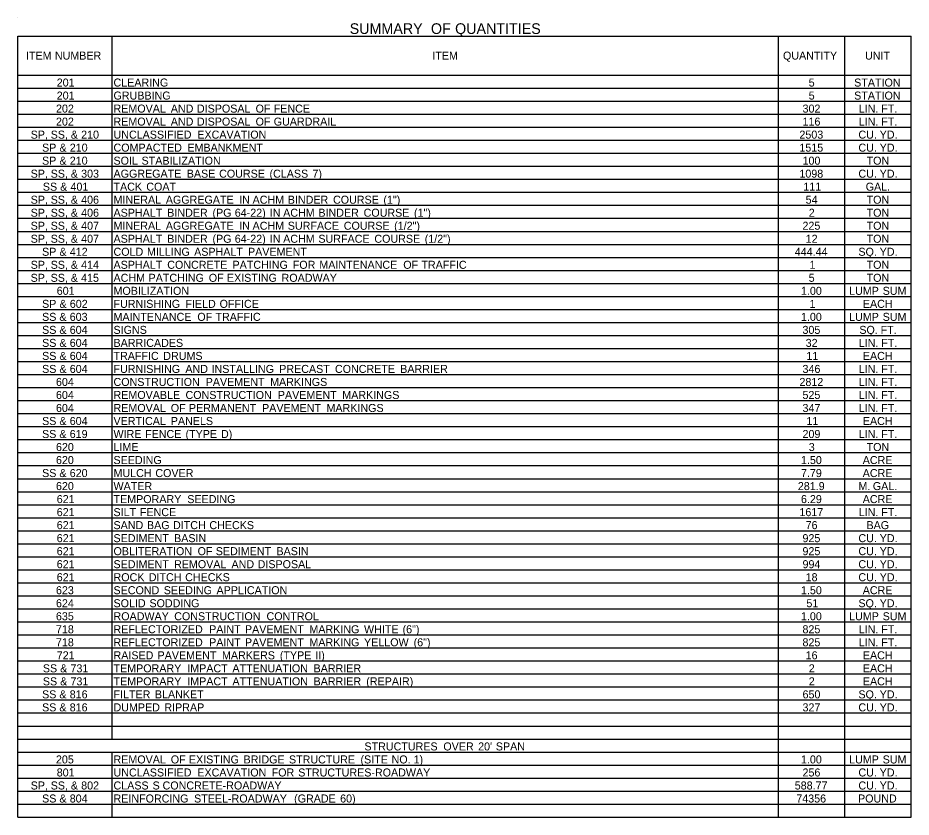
# Model space of a CAD drawing. Extents: x 120 to 5602, y 34 to 1048.
# Drawn here: x 4195 to 4864, y 243 to 842 of the extents above; entities that cross this region are included whole.
import ezdxf

# ---------------------------------------------------------------- set-up
doc = ezdxf.new("R2010")
doc.units = 0
doc.layers.add('Default', color=7, linetype='Continuous')
doc.layers.add('STAMP', color=7, linetype='Continuous')

msp = doc.modelspace()

# ---------------------------------------------------------------- linework, layer by layer
at = {"layer": 'Default'}
for p, q in [((4194.64, 828.32), (4265.32, 828.32)), ((4194.64, 828.32), (4863.97, 828.32)), ((4194.64, 243.32), (4194.64, 828.32)), ((4265.32, 301.82), (4265.32, 828.32)), ((4764.52, 243.32), (4764.52, 828.32)), ((4814.25, 243.32), (4814.25, 828.32)), ((4814.25, 301.82), (4814.25, 828.32)), ((4863.97, 243.32), (4863.97, 828.32)), ((4194.64, 799.07), (4863.97, 799.07)), ((4265.32, 301.82), (4265.32, 799.07)), ((4764.52, 301.82), (4764.52, 799.07)), ((4194.64, 789.32), (4863.97, 789.32)), ((4194.64, 779.57), (4863.97, 779.57)), ((4194.64, 769.82), (4863.97, 769.82)), ((4194.64, 760.07), (4863.97, 760.07)), ((4194.64, 750.32), (4863.97, 750.32)), ((4194.64, 740.57), (4863.97, 740.57)), ((4194.64, 730.82), (4863.97, 730.82)), ((4194.64, 721.07), (4863.97, 721.07)), ((4194.64, 711.32), (4863.97, 711.32)), ((4194.64, 701.57), (4863.97, 701.57)), ((4194.64, 691.82), (4863.97, 691.82)), ((4194.64, 682.07), (4863.97, 682.07)), ((4194.64, 672.32), (4863.97, 672.32)), ((4194.64, 662.57), (4863.97, 662.57)), ((4194.64, 652.82), (4863.97, 652.82)), ((4194.64, 643.07), (4863.97, 643.07)), ((4194.64, 633.32), (4863.97, 633.32)), ((4194.64, 623.57), (4863.97, 623.57)), ((4194.64, 613.82), (4863.97, 613.82)), ((4194.64, 604.07), (4863.97, 604.07)), ((4194.64, 594.32), (4863.97, 594.32)), ((4194.64, 584.57), (4863.97, 584.57)), ((4194.64, 574.82), (4863.97, 574.82)), ((4194.64, 565.07), (4863.97, 565.07)), ((4194.64, 555.32), (4863.97, 555.32)), ((4194.64, 545.57), (4863.97, 545.57)), ((4194.64, 535.82), (4863.97, 535.82)), ((4194.64, 526.07), (4863.97, 526.07)), ((4194.64, 516.32), (4863.97, 516.32)), ((4194.64, 506.57), (4863.97, 506.57)), ((4194.64, 496.82), (4863.97, 496.82)), ((4194.64, 487.07), (4863.97, 487.07)), ((4194.64, 477.32), (4863.97, 477.32)), ((4194.64, 467.57), (4863.97, 467.57)), ((4194.64, 457.82), (4863.97, 457.82)), ((4194.64, 448.07), (4863.97, 448.07)), ((4194.64, 438.32), (4863.97, 438.32)), ((4194.64, 428.57), (4863.97, 428.57)), ((4194.64, 418.82), (4863.97, 418.82)), ((4194.64, 409.07), (4863.97, 409.07)), ((4194.64, 399.32), (4863.97, 399.32)), ((4194.64, 389.57), (4863.97, 389.57)), ((4194.64, 379.82), (4863.97, 379.82)), ((4194.64, 370.07), (4863.97, 370.07)), ((4194.64, 360.32), (4863.97, 360.32)), ((4194.64, 350.57), (4863.97, 350.57)), ((4194.64, 340.82), (4863.97, 340.82)), ((4194.64, 331.07), (4863.97, 331.07)), ((4194.64, 321.32), (4863.97, 321.32)), ((4194.64, 311.57), (4863.97, 311.57)), ((4194.64, 301.82), (4863.97, 301.82)), ((4814.25, 301.82), (4863.97, 301.82)), ((4194.64, 292.07), (4863.97, 292.07)), ((4265.32, 243.32), (4265.32, 292.07)), ((4265.32, 243.32), (4265.32, 292.07)), ((4764.52, 243.32), (4764.52, 292.07)), ((4814.25, 243.32), (4814.25, 292.07)), ((4194.64, 282.32), (4863.97, 282.32)), ((4194.64, 272.57), (4863.97, 272.57)), ((4194.64, 262.82), (4863.97, 262.82)), ((4194.64, 253.07), (4863.97, 253.07)), ((4194.64, 243.32), (4863.97, 243.32))]:
    msp.add_line(p, q, dxfattribs=at)
at = {"layer": 'STAMP'}
msp.add_line((4194.64, 841.97), (4194.64, 841.97), dxfattribs=at)

# ---------------------------------------------------------------- texts
at = {"layer": 'Default'}
for s, height, p in [(' SUMMARY', 8, (4440.3, 829.92)), (' OF', 8, (4501.18, 829.92)), (' QUANTITIES', 8, (4519.29, 829.92)), ('ITEM', 6, (4200.72, 810.69)), (' NUMBER', 6, (4220.15, 810.69)), ('ITEM', 6, (4505.21, 810.69)), ('QUANTITY', 6, (4767.95, 810.69)), ('UNIT', 6, (4829.42, 810.69)), ('201', 6, (4223.76, 790.52)), ('CLEARING', 6, (4266.3, 790.52)), ('5', 6, (4787.22, 790.52)), ('STATION', 6, (4821.29, 790.52)), ('201', 6, (4223.76, 780.77)), ('GRUBBING', 6, (4266.3, 780.77)), ('5', 6, (4787.22, 780.77)), ('STATION', 6, (4821.29, 780.77)), ('202', 6, (4223.21, 771.02)), ('REMOVAL', 6, (4266.3, 771.02)), (' AND', 6, (4307, 771.02)), (' DISPOSAL', 6, (4326.58, 771.02)), (' OF', 6, (4370.55, 771.02)), (' FENCE', 6, (4384.13, 771.02)), ('302', 6, (4782.62, 771.02)), ('LIN.', 6, (4824.71, 771.02)), (' FT.', 6, (4839.35, 771.02)), ('202', 6, (4223.21, 761.27)), ('REMOVAL', 6, (4266.3, 761.27)), (' AND', 6, (4307, 761.27)), (' DISPOSAL', 6, (4326.58, 761.27)), (' OF', 6, (4370.55, 761.27)), (' GUARDRAIL', 6, (4384.13, 761.27)), ('116', 6, (4782.59, 761.27)), ('LIN.', 6, (4824.71, 761.27)), (' FT.', 6, (4839.35, 761.27)), ('SP,', 6, (4204.23, 751.52)), (' SS,', 6, (4217, 751.52)), (' &', 6, (4232.09, 751.52)), (' 210', 6, (4239.82, 751.52)), ('UNCLASSIFIED', 6, (4266.3, 751.52)), (' EXCAVATION', 6, (4326.88, 751.52)), ('2503', 6, (4780.26, 751.52)), ('CU.', 6, (4824.47, 751.52)), (' YD.', 6, (4838.18, 751.52)), ('SP', 6, (4212.75, 741.77)), (' &', 6, (4223.57, 741.77)), (' 210', 6, (4231.3, 741.77)), ('COMPACTED', 6, (4266.3, 741.77)), (' EMBANKMENT', 6, (4319.42, 741.77)), ('1515', 6, (4780.23, 741.77)), ('CU.', 6, (4824.47, 741.77)), (' YD.', 6, (4838.18, 741.77)), ('SP', 6, (4212.75, 732.02)), (' &', 6, (4223.57, 732.02)), (' 210', 6, (4231.3, 732.02)), ('SOIL', 6, (4266.3, 732.02)), (' STABILIZATION', 6, (4285.1, 732.02)), ('100', 6, (4782.6, 732.02)), ('TON', 6, (4830.6, 732.02)), ('SP,', 6, (4204.22, 722.27)), (' SS,', 6, (4216.99, 722.27)), (' &', 6, (4232.08, 722.27)), (' 303', 6, (4239.81, 722.27)), ('AGGREGATE', 6, (4266.3, 722.27)), (' BASE', 6, (4318.96, 722.27)), (' COURSE', 6, (4343.21, 722.27)), (' (CLASS', 6, (4380.97, 722.27)), (' 7)', 6, (4413.14, 722.27)), ('1098', 6, (4780.25, 722.27)), ('CU.', 6, (4824.47, 722.27)), (' YD.', 6, (4838.18, 722.27)), ('SS', 6, (4213.36, 712.52)), (' &', 6, (4224.1, 712.52)), (' 401', 6, (4231.83, 712.52)), ('TACK', 6, (4266.3, 712.52)), (' COAT', 6, (4288.64, 712.52)), ('111', 6, (4783.17, 712.52)), ('GAL.', 6, (4829.93, 712.52)), ('SP,', 6, (4204.22, 702.77)), (' SS,', 6, (4216.99, 702.77)), (' &', 6, (4232.08, 702.77)), (' 406', 6, (4239.81, 702.77)), ('MINERAL', 6, (4266.3, 702.77)), (' AGGREGATE', 6, (4303.27, 702.77)), (' IN', 6, (4358.26, 702.77)), (' ACHM', 6, (4368.28, 702.77)), (' BINDER', 6, (4394.67, 702.77)), (' COURSE', 6, (4428.56, 702.77)), (' (1")', 6, (4466.31, 702.77)), ('54', 6, (4784.93, 702.77)), ('TON', 6, (4830.6, 702.77)), ('SP,', 6, (4204.22, 693.02)), (' SS,', 6, (4216.99, 693.02)), (' &', 6, (4232.08, 693.02)), (' 406', 6, (4239.81, 693.02)), ('ASPHALT', 6, (4266.3, 693.02)), (' BINDER', 6, (4304.34, 693.02)), (' (PG', 6, (4338.23, 693.02)), (' 64-22)', 6, (4354.94, 693.02)), (' IN', 6, (4381.18, 693.02)), (' ACHM', 6, (4391.2, 693.02)), (' BINDER', 6, (4417.59, 693.02)), (' COURSE', 6, (4451.48, 693.02)), (' (1")', 6, (4489.23, 693.02)), ('2', 6, (4787.28, 693.02)), ('TON', 6, (4830.6, 693.02)), (' (1/2")', 6, (4474.36, 683.27)), ('SP,', 6, (4204.22, 683.27)), (' SS,', 6, (4216.99, 683.27)), (' &', 6, (4232.08, 683.27)), (' 407', 6, (4239.81, 683.27)), ('MINERAL', 6, (4266.3, 683.27)), (' AGGREGATE', 6, (4303.27, 683.27)), (' IN', 6, (4358.26, 683.27)), (' ACHM', 6, (4368.28, 683.27)), (' SURFACE', 6, (4394.67, 683.27)), (' COURSE', 6, (4436.61, 683.27)), ('225', 6, (4782.56, 683.27)), ('TON', 6, (4830.6, 683.27)), ('SP,', 6, (4204.22, 673.52)), (' SS,', 6, (4216.99, 673.52)), (' &', 6, (4232.08, 673.52)), (' 407', 6, (4239.81, 673.52)), ('ASPHALT', 6, (4266.3, 673.52)), (' BINDER', 6, (4304.34, 673.52)), (' (PG', 6, (4338.23, 673.52)), (' 64-22)', 6, (4354.94, 673.52)), (' IN', 6, (4381.18, 673.52)), (' ACHM', 6, (4391.2, 673.52)), (' SURFACE', 6, (4417.59, 673.52)), (' COURSE', 6, (4459.53, 673.52)), (' (1/2")', 6, (4497.28, 673.52)), ('12', 6, (4784.95, 673.52)), ('TON', 6, (4830.6, 673.52)), ('SP', 6, (4212.77, 663.77)), (' &', 6, (4223.59, 663.77)), (' 412', 6, (4231.32, 663.77)), ('COLD', 6, (4266.3, 663.77)), (' MILLING', 6, (4289.14, 663.77)), (' ASPHALT', 6, (4324.48, 663.77)), (' PAVEMENT', 6, (4364.85, 663.77)), ('444.44', 6, (4776.77, 663.77)), ('SQ.', 6, (4824.47, 663.77)), (' YD.', 6, (4838.18, 663.77)), ('SP,', 6, (4204.23, 654.02)), (' SS,', 6, (4217, 654.02)), (' &', 6, (4232.1, 654.02)), (' 414', 6, (4239.83, 654.02)), ('ASPHALT', 6, (4266.3, 654.02)), (' CONCRETE', 6, (4304.34, 654.02)), (' PATCHING', 6, (4353.27, 654.02)), (' FOR', 6, (4398.39, 654.02)), (' MAINTENANCE', 6, (4418.3, 654.02)), (' OF', 6, (4481.2, 654.02)), (' TRAFFIC', 6, (4494.79, 654.02)), ('1', 6, (4787.83, 654.02)), ('TON', 6, (4830.6, 654.02)), ('SP,', 6, (4204.2, 644.27)), (' SS,', 6, (4216.96, 644.27)), (' &', 6, (4232.06, 644.27)), (' 415', 6, (4239.79, 644.27)), ('ACHM', 6, (4266.3, 644.27)), (' PATCHING', 6, (4290.35, 644.27)), (' OF', 6, (4335.48, 644.27)), (' EXISTING', 6, (4349.06, 644.27)), (' ROADWAY', 6, (4390, 644.27)), ('5', 6, (4787.22, 644.27)), ('TON', 6, (4830.6, 644.27)), ('601', 6, (4223.76, 634.52)), ('MOBILIZATION', 6, (4266.3, 634.52)), ('1.00', 6, (4781.43, 634.52)), ('LUMP', 6, (4817.48, 634.52)), (' SUM', 6, (4840.41, 634.52)), ('SP', 6, (4212.77, 624.77)), (' &', 6, (4223.59, 624.77)), (' 602', 6, (4231.32, 624.77)), ('FURNISHING', 6, (4266.3, 624.77)), (' FIELD', 6, (4317.94, 624.77)), (' OFFICE', 6, (4343.58, 624.77)), ('1', 6, (4787.83, 624.77)), ('EACH', 6, (4827.8, 624.77)), ('SS', 6, (4212.78, 615.02)), (' &', 6, (4223.52, 615.02)), (' 603', 6, (4231.25, 615.02)), ('MAINTENANCE', 6, (4266.3, 615.02)), (' OF', 6, (4326.87, 615.02)), (' TRAFFIC', 6, (4340.46, 615.02)), ('1.00', 6, (4781.43, 615.02)), ('LUMP', 6, (4817.48, 615.02)), (' SUM', 6, (4840.41, 615.02)), ('SS', 6, (4212.79, 605.27)), (' &', 6, (4223.54, 605.27)), (' 604', 6, (4231.27, 605.27)), ('SIGNS', 6, (4266.3, 605.27)), ('305', 6, (4782.56, 605.27)), ('SQ.', 6, (4825.17, 605.27)), (' FT.', 6, (4838.88, 605.27)), ('SS', 6, (4212.79, 595.52)), (' &', 6, (4223.54, 595.52)), (' 604', 6, (4231.27, 595.52)), ('BARRICADES', 6, (4266.3, 595.52)), ('32', 6, (4784.95, 595.52)), ('LIN.', 6, (4824.71, 595.52)), (' FT.', 6, (4839.35, 595.52)), ('SS', 6, (4212.79, 585.77)), (' &', 6, (4223.54, 585.77)), (' 604', 6, (4231.27, 585.77)), ('TRAFFIC', 6, (4266.3, 585.77)), (' DRUMS', 6, (4301.36, 585.77)), ('11', 6, (4785.5, 585.77)), ('EACH', 6, (4827.8, 585.77)), ('SS', 6, (4212.79, 576.02)), (' &', 6, (4223.54, 576.02)), (' 604', 6, (4231.27, 576.02)), ('FURNISHING', 6, (4266.3, 576.02)), (' AND', 6, (4317.94, 576.02)), (' INSTALLING', 6, (4337.52, 576.02)), (' PRECAST', 6, (4388.24, 576.02)), (' CONCRETE', 6, (4430, 576.02)), (' BARRIER', 6, (4478.93, 576.02)), ('346', 6, (4782.59, 576.02)), ('LIN.', 6, (4824.71, 576.02)), (' FT.', 6, (4839.35, 576.02)), ('604', 6, (4223.19, 566.27)), ('CONSTRUCTION', 6, (4266.3, 566.27)), (' PAVEMENT', 6, (4333.15, 566.27)), (' MARKINGS', 6, (4381.43, 566.27)), ('2812', 6, (4780.29, 566.27)), ('LIN.', 6, (4824.71, 566.27)), (' FT.', 6, (4839.35, 566.27)), ('604', 6, (4223.19, 556.52)), ('REMOVABLE', 6, (4266.3, 556.52)), (' CONSTRUCTION', 6, (4318.03, 556.52)), (' PAVEMENT', 6, (4387.21, 556.52)), (' MARKINGS', 6, (4435.5, 556.52)), ('525', 6, (4782.56, 556.52)), ('LIN.', 6, (4824.71, 556.52)), (' FT.', 6, (4839.35, 556.52)), ('604', 6, (4223.19, 546.77)), ('REMOVAL', 6, (4266.3, 546.77)), (' OF', 6, (4307, 546.77)), (' PERMANENT', 6, (4320.59, 546.77)), (' PAVEMENT', 6, (4375.39, 546.77)), (' MARKINGS', 6, (4423.67, 546.77)), ('347', 6, (4782.59, 546.77)), ('LIN.', 6, (4824.71, 546.77)), (' FT.', 6, (4839.35, 546.77)), ('SS', 6, (4212.79, 537.02)), (' &', 6, (4223.54, 537.02)), (' 604', 6, (4231.27, 537.02)), ('VERTICAL', 6, (4266.3, 537.02)), (' PANELS', 6, (4307, 537.02)), ('11', 6, (4785.5, 537.02)), ('EACH', 6, (4827.8, 537.02)), ('SS', 6, (4212.77, 527.27)), (' &', 6, (4223.52, 527.27)), (' 619', 6, (4231.25, 527.27)), ('WIRE', 6, (4266.3, 527.27)), (' FENCE', 6, (4287.74, 527.27)), (' (TYPE', 6, (4318.03, 527.27)), (' D)', 6, (4344.6, 527.27)), ('209', 6, (4782.58, 527.27)), ('LIN.', 6, (4824.71, 527.27)), (' FT.', 6, (4839.35, 527.27)), ('620', 6, (4223.19, 517.52)), ('LIME', 6, (4266.3, 517.52)), ('3', 6, (4787.25, 517.52)), ('TON', 6, (4830.6, 517.52)), ('620', 6, (4223.19, 507.77)), ('SEEDING', 6, (4266.3, 507.77)), ('1.50', 6, (4781.43, 507.77)), ('ACRE', 6, (4827.69, 507.77)), ('SS', 6, (4212.79, 498.02)), (' &', 6, (4223.54, 498.02)), (' 620', 6, (4231.26, 498.02)), ('MULCH', 6, (4266.3, 498.02)), (' COVER', 6, (4295.43, 498.02)), ('7.79', 6, (4781.42, 498.02)), ('ACRE', 6, (4827.69, 498.02)), ('620', 6, (4223.19, 488.27)), ('WATER', 6, (4266.3, 488.27)), ('281.9', 6, (4779.09, 488.27)), ('M.', 6, (4824.47, 488.27)), (' GAL.', 6, (4833.05, 488.27)), ('621', 6, (4223.76, 478.52)), ('TEMPORARY', 6, (4266.3, 478.52)), (' SEEDING', 6, (4319.34, 478.52)), ('6.29', 6, (4781.42, 478.52)), ('ACRE', 6, (4827.69, 478.52)), ('621', 6, (4223.76, 468.77)), ('SILT', 6, (4266.3, 468.77)), (' FENCE', 6, (4283.83, 468.77)), ('1617', 6, (4780.26, 468.77)), ('LIN.', 6, (4824.71, 468.77)), (' FT.', 6, (4839.35, 468.77)), ('621', 6, (4223.76, 459.02)), ('SAND', 6, (4266.3, 459.02)), (' BAG', 6, (4289.15, 459.02)), (' DITCH', 6, (4308.65, 459.02)), (' CHECKS', 6, (4335.92, 459.02)), ('76', 6, (4784.92, 459.02)), ('BAG', 6, (4830.52, 459.02)), ('621', 6, (4223.76, 449.27)), ('SEDIMENT', 6, (4266.3, 449.27)), (' BASIN', 6, (4309.45, 449.27)), ('925', 6, (4782.56, 449.27)), ('CU.', 6, (4824.47, 449.27)), (' YD.', 6, (4838.18, 449.27)), ('621', 6, (4223.76, 439.52)), ('OBLITERATION', 6, (4266.3, 439.52)), (' OF', 6, (4327.1, 439.52)), (' SEDIMENT', 6, (4340.69, 439.52)), (' BASIN', 6, (4386.17, 439.52)), ('925', 6, (4782.56, 439.52)), ('CU.', 6, (4824.47, 439.52)), (' YD.', 6, (4838.18, 439.52)), ('621', 6, (4223.76, 429.77)), ('SEDIMENT', 6, (4266.3, 429.77)), (' REMOVAL', 6, (4309.45, 429.77)), (' AND', 6, (4352.48, 429.77)), (' DISPOSAL', 6, (4372.06, 429.77)), ('994', 6, (4782.6, 429.77)), ('CU.', 6, (4824.47, 429.77)), (' YD.', 6, (4838.18, 429.77)), ('621', 6, (4223.76, 420.02)), ('ROCK', 6, (4266.3, 420.02)), (' DITCH', 6, (4290.5, 420.02)), (' CHECKS', 6, (4317.77, 420.02)), ('18', 6, (4784.91, 420.02)), ('CU.', 6, (4824.47, 420.02)), (' YD.', 6, (4838.18, 420.02)), ('623', 6, (4223.18, 410.27)), ('SECOND', 6, (4266.3, 410.27)), (' SEEDING', 6, (4301.72, 410.27)), (' APPLICATION', 6, (4341.26, 410.27)), ('1.50', 6, (4781.43, 410.27)), ('ACRE', 6, (4827.69, 410.27)), ('624', 6, (4223.19, 400.52)), ('SOLID', 6, (4266.3, 400.52)), (' SODDING', 6, (4291.01, 400.52)), ('51', 6, (4785.5, 400.52)), ('SQ.', 6, (4824.47, 400.52)), (' YD.', 6, (4838.18, 400.52)), ('635', 6, (4223.16, 390.77)), ('ROADWAY', 6, (4266.3, 390.77)), (' CONSTRUCTION', 6, (4309.56, 390.77)), (' CONTROL', 6, (4378.73, 390.77)), ('1.00', 6, (4781.43, 390.77)), ('LUMP', 6, (4817.48, 390.77)), (' SUM', 6, (4840.41, 390.77)), ('718', 6, (4223.17, 381.02)), ('REFLECTORIZED', 6, (4266.3, 381.02)), (' PAINT', 6, (4335.72, 381.02)), (' PAVEMENT', 6, (4362.57, 381.02)), (' MARKING', 6, (4410.86, 381.02)), (' WHITE', 6, (4451.79, 381.02)), (' (6")', 6, (4480.67, 381.02)), ('825', 6, (4782.56, 381.02)), ('LIN.', 6, (4824.71, 381.02)), (' FT.', 6, (4839.35, 381.02)), ('718', 6, (4223.17, 371.27)), ('REFLECTORIZED', 6, (4266.3, 371.27)), (' PAINT', 6, (4335.72, 371.27)), (' PAVEMENT', 6, (4362.57, 371.27)), (' MARKING', 6, (4410.86, 371.27)), (' YELLOW', 6, (4451.79, 371.27)), (' (6")', 6, (4488.96, 371.27)), ('825', 6, (4782.56, 371.27)), ('LIN.', 6, (4824.71, 371.27)), (' FT.', 6, (4839.35, 371.27)), ('721', 6, (4223.76, 361.52)), ('RAISED', 6, (4266.3, 361.52)), (' PAVEMENT', 6, (4297.07, 361.52)), (' MARKERS', 6, (4345.35, 361.52)), (' (TYPE', 6, (4388.7, 361.52)), (' II)', 6, (4415.27, 361.52)), ('16', 6, (4784.92, 361.52)), ('EACH', 6, (4827.8, 361.52)), ('SS', 6, (4213.36, 351.77)), (' &', 6, (4224.1, 351.77)), (' 731', 6, (4231.83, 351.77)), ('TEMPORARY', 6, (4266.3, 351.77)), (' IMPACT', 6, (4319.34, 351.77)), (' ATTENUATION', 6, (4353.17, 351.77)), (' BARRIER', 6, (4413.97, 351.77)), ('2', 6, (4787.28, 351.77)), ('EACH', 6, (4827.8, 351.77)), ('SS', 6, (4213.36, 342.02)), (' 731', 6, (4231.83, 342.02)), ('TEMPORARY', 6, (4266.3, 342.02)), (' IMPACT', 6, (4319.34, 342.02)), (' ATTENUATION', 6, (4353.17, 342.02)), (' (REPAIR)', 6, (4453.46, 342.02)), ('2', 6, (4787.28, 342.02)), ('EACH', 6, (4827.8, 342.02)), (' &', 6, (4224.1, 342.02)), (' BARRIER', 6, (4413.97, 342.02)), ('SS', 6, (4212.78, 332.27)), (' &', 6, (4223.52, 332.27)), (' 816', 6, (4231.25, 332.27)), ('FILTER', 6, (4266.3, 332.27)), (' BLANKET', 6, (4295.06, 332.27)), ('650', 6, (4782.6, 332.27)), ('SQ.', 6, (4824.47, 332.27)), (' YD.', 6, (4838.18, 332.27)), ('SS', 6, (4212.78, 322.52)), (' &', 6, (4223.52, 322.52)), (' 816', 6, (4231.25, 322.52)), ('DUMPED', 6, (4266.3, 322.52)), (' RIPRAP', 6, (4302.18, 322.52)), ('327', 6, (4782.59, 322.52)), ('CU.', 6, (4824.47, 322.52)), (' YD.', 6, (4838.18, 322.52)), ('STRUCTURES', 6, (4454.34, 293.27)), (' OVER', 6, (4511.23, 293.27)), (" 20'", 6, (4537.28, 293.27)), (' SPAN', 6, (4550.55, 293.27)), ('205', 6, (4223.16, 283.52)), ('REMOVAL', 6, (4266.3, 283.52)), (' OF', 6, (4307, 283.52)), (' EXISTING', 6, (4320.59, 283.52)), (' BRIDGE', 6, (4361.52, 283.52)), (' STRUCTURE', 6, (4395.54, 283.52)), (' (SITE', 6, (4449.13, 283.52)), (' NO.', 6, (4472.43, 283.52)), (' 1)', 6, (4488.93, 283.52)), ('1.00', 6, (4781.43, 283.52)), ('LUMP', 6, (4817.48, 283.52)), (' SUM', 6, (4840.41, 283.52)), ('801', 6, (4223.76, 273.77)), ('UNCLASSIFIED', 6, (4266.3, 273.77)), (' EXCAVATION', 6, (4326.88, 273.77)), (' FOR', 6, (4382.57, 273.77)), (' STRUCTURES-ROADWAY', 6, (4402.48, 273.77)), ('256', 6, (4782.59, 273.77)), ('CU.', 6, (4824.47, 273.77)), (' YD.', 6, (4838.18, 273.77)), ('SP,', 6, (4204.25, 264.02)), (' SS,', 6, (4217.02, 264.02)), (' &', 6, (4232.11, 264.02)), (' 802', 6, (4239.84, 264.02)), ('CLASS', 6, (4266.3, 264.02)), (' S', 6, (4293.35, 264.02)), (' CONCRETE-ROADWAY', 6, (4300.83, 264.02)), ('588.77', 6, (4776.76, 264.02)), ('CU.', 6, (4824.47, 264.02)), (' YD.', 6, (4838.18, 264.02)), ('SS', 6, (4212.79, 254.27)), (' &', 6, (4223.54, 254.27)), (' 804', 6, (4231.27, 254.27)), ('REINFORCING', 6, (4266.3, 254.27)), (' STEEL-ROADWAY', 6, (4324.46, 254.27)), (' (GRADE', 6, (4399.4, 254.27)), (' 60)', 6, (4433.88, 254.27)), ('74356', 6, (4777.93, 254.27)), ('POUND', 6, (4824.19, 254.27))]:
    msp.add_text(s, height=height, dxfattribs=at).set_placement(p)

doc.saveas('drawing.dxf')
